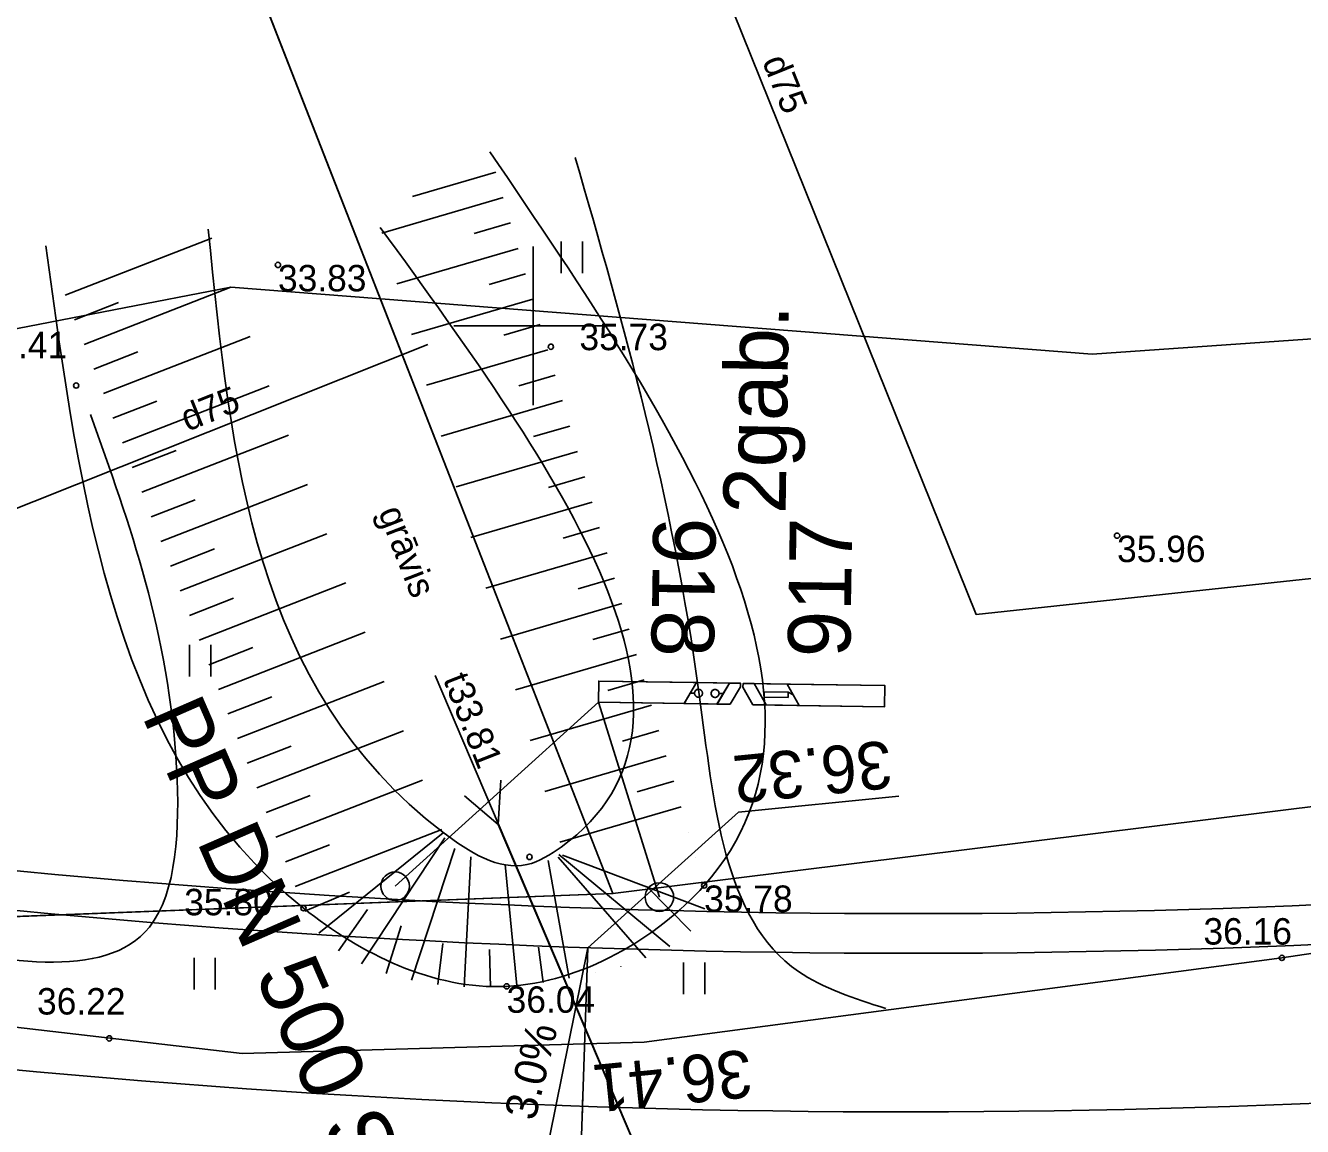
# Model space of a CAD drawing. Extents: x 469981 to 472086, y 246785 to 247785.
# Drawn here: x 470990.4 to 471014.55, y 247184.86 to 247205.68 of the extents above; entities that cross this region are included whole.
import ezdxf

# ---------------------------------------------------------------- set-up
doc = ezdxf.new("R2010")
doc.units = 0
for name, color, linetype in [('0_922', 7, 'Continuous'), ('0_Asfalta_mala', 7, 'Continuous'), ('0_Asfalta_Nomale', 7, 'Continuous'), ('0_caurtekas', 7, 'Continuous'), ('0_Ruut_Braukt', 7, 'Continuous'), ('0_Ruut_nomale', 7, 'Continuous'), ('0_vertikals', 7, 'Continuous'), ('0_vertkals_cipari', 7, 'Continuous'), ('0_Ziimes', 7, 'Continuous'), ('21', 7, 'Continuous'), ('6_piketaza', 7, 'Continuous'), ('CELI_CMAL_####_####_#', 7, 'Continuous'), ('DREN_ELEM_####_####_#', 7, 'Continuous'), ('DREN_VADP_KLKT_####_#', 7, 'Continuous'), ('DREN_VADP_KLKT_TKST_#', 7, 'Continuous'), ('GEOD_ELEM_####_####_#', 7, 'Continuous'), ('HIDG_GRAV_####_####_#', 7, 'Continuous'), ('HIDG_GRAV_####_TKST_#', 7, 'Continuous'), ('RAMI_UZMR_####_####_#', 7, 'Continuous'), ('RELJ_AATZ_####_TKST_#', 7, 'Continuous'), ('RELJ_ELEM_####_####_#', 7, 'Continuous'), ('RELJ_NOGA_####_####_#', 7, 'Continuous'), ('ROBZ_IERR_####_####_#', 7, 'Continuous'), ('ROBZ_PROJ_####_####_#', 7, 'Continuous'), ('TERT_ELEM_####_####_#', 7, 'Continuous'), ('TERT_KONT_####_####_#', 7, 'Continuous'), ('Z_PILD_MELNS', 7, 'Continuous')]:
    doc.layers.add(name, color=color, linetype=linetype)

msp = doc.modelspace()

# ---------------------------------------------------------------- linework, layer by layer
at = {"layer": '0_922'}
msp.add_arc((471007.123, 247365.136), 180, 250.3373, 277.44649, dxfattribs=at)
at = {"layer": '0_Asfalta_mala'}
for radius in [177, 183]:
    msp.add_arc((471007.123, 247365.136), radius, 250.3373, 277.44649, dxfattribs=at)
at = {"layer": '0_Asfalta_Nomale'}
for radius in [176.25, 183.75]:
    msp.add_arc((471007.123, 247365.136), radius, 250.3373, 277.44649, dxfattribs=at)
at = {"layer": '0_caurtekas'}
msp.add_line((470998.149, 247193.392), (471004.628, 247178.166), dxfattribs=at)
at = {"layer": '0_Ruut_Braukt'}
for radius in [177, 183]:
    msp.add_arc((471007.123, 247365.136), radius, 250.3373, 277.44649, dxfattribs=at)
at = {"layer": '0_Ruut_nomale'}
for radius, start, end in [(176.25, 250.3373, 277.44649), (177, 250.33757, 277.4462), (183, 250.33757, 277.44649), (183.75, 250.3373, 277.44649)]:
    msp.add_arc((471007.123, 247365.136), radius, start, end, dxfattribs=at)
at = {"layer": '0_vertikals'}
for p, q in [((471003.884, 247190.806), (471006.915, 247191.11)), ((471001.038, 247188.24), (471003.884, 247190.806))]:
    msp.add_line(p, q, dxfattribs=at)
msp.add_lwpolyline([(471001.038, 247188.24), (470999.832, 247182.28), (471000.831, 247182.244)], close=True, dxfattribs=at)
at = {"layer": '0_Ziimes'}
for q in [(470997.392, 247189.405), (471002.388, 247189.199)]:
    msp.add_line((471001.235, 247192.883), q, dxfattribs=at)
for centre in [(470997.392, 247189.405), (470997.392, 247189.405), (471002.388, 247189.199), (471002.388, 247189.199)]:
    msp.add_circle(centre, 0.27, dxfattribs=at)
at = {"layer": '21'}
msp.add_arc((471007.123, 247365.136), 180, 250.3373, 277.44649, dxfattribs=at)
at = {"layer": '6_piketaza'}
msp.add_lwpolyline([(471000.926, 247184.992), (471000.943, 247185.492)], dxfattribs=at)
at = {"layer": 'CELI_CMAL_####_####_#'}
msp.add_lwpolyline([(470887.869, 247219.351), (470907.988, 247212.254), (470934.743, 247202.499), (470962.898, 247192.42), (470982.559, 247187.627), (470994.5, 247186.238), (471002.099, 247186.455), (471014.161, 247188.048), (471038.308, 247191.645)], dxfattribs=at)
at = {"layer": 'DREN_ELEM_####_####_#'}
msp.add_lwpolyline([(470999.391, 247191.41), (470999.34, 247190.573), (470998.701, 247191.116)], dxfattribs=at)
msp.add_lwpolyline([(470999.391, 247191.41), (470999.34, 247190.573), (470998.701, 247191.116)], dxfattribs=at)
at = {"layer": 'DREN_VADP_KLKT_####_#'}
for points in [[(470998.012, 247199.651), (470980.588, 247192.708), (470867.536, 247231.459)], [(470999.031, 247217.751), (471008.378, 247194.545), (471079.006, 247202.129)], [(471024.755, 247145.454), (471007.332, 247171.821), (470999.34, 247190.573)]]:
    msp.add_lwpolyline(points, dxfattribs=at)
at = {"layer": 'GEOD_ELEM_####_####_#'}
for p, q in [((471000, 247201.5), (471000, 247200)), ((470998.5, 247200), (471000, 247200)), ((471000, 247200), (471000, 247198.5)), ((471000, 247200), (471001.5, 247200))]:
    msp.add_line(p, q, dxfattribs=at)
at = {"layer": 'HIDG_GRAV_####_####_#'}
msp.add_spline([(470993.859, 247201.832), (470998.294, 247190.426), (470999.883, 247189.814), (471000.533, 247190.146), (470997.111, 247201.864)], degree=3, dxfattribs=at)
at = {"layer": 'RAMI_UZMR_####_####_#'}
msp.add_lwpolyline([(470560.64, 247175.144), (470793.366, 247232.231), (470822.25, 247233), (470855.497, 247231.608), (470869.75, 247235.5), (470872.288, 247238.827), (470875.523, 247240.24), (470882.387, 247236.327), (470885.36, 247235.904), (470900.348, 247222.872), (470947.872, 247208.875), (470978.25, 247197.629), (470994.287, 247200.731), (471010.572, 247199.465), (471044.448, 247201.846)], dxfattribs=at)
at = {"layer": 'RELJ_ELEM_####_####_#'}
for centre in [(470995.176, 247201.154), (471000.337, 247199.607), (470991.36, 247198.873), (471011.043, 247196.034), (470999.933, 247189.959), (471003.235, 247189.418), (470995.658, 247188.99), (471014.16, 247188.049), (470999.5, 247187.511), (470991.985, 247186.526)]:
    msp.add_circle(centre, 0.05, dxfattribs=at)
at = {"layer": 'RELJ_NOGA_####_####_#'}
for p, q in [((470999.295, 247202.908), (470997.718, 247202.447)), ((470999.435, 247202.428), (470997.142, 247201.758)), ((470999.576, 247201.948), (470998.887, 247201.747)), ((470990.787, 247201.516), (470990.788, 247201.516)), ((470991.149, 247200.584), (470993.924, 247201.663)), ((470999.716, 247201.468), (470997.422, 247200.798)), ((470990.968, 247201.05), (470990.968, 247201.05)), ((470999.856, 247200.988), (470999.168, 247200.787)), ((470991.512, 247199.652), (470994.287, 247200.731)), ((470999.996, 247200.508), (470997.702, 247199.838)), ((470991.33, 247200.118), (470992.163, 247200.442)), ((471000.136, 247200.028), (470999.448, 247199.827)), ((470991.874, 247198.72), (470994.649, 247199.799)), ((471000.276, 247199.548), (470997.983, 247198.878)), ((470991.693, 247199.186), (470992.525, 247199.51)), ((471000.417, 247199.068), (470999.728, 247198.867)), ((470992.237, 247197.788), (470995.012, 247198.867)), ((470992.055, 247198.254), (470992.888, 247198.578)), ((471000.557, 247198.588), (470998.263, 247197.918)), ((471000.697, 247198.108), (471000.009, 247197.907)), ((470992.599, 247196.856), (470995.374, 247197.935)), ((470992.418, 247197.322), (470993.25, 247197.646)), ((471000.837, 247197.628), (470998.543, 247196.958)), ((471000.977, 247197.148), (471000.289, 247196.947)), ((470992.961, 247195.924), (470995.737, 247197.003)), ((470992.78, 247196.39), (470993.613, 247196.714)), ((471001.117, 247196.668), (470998.824, 247195.999)), ((471001.258, 247196.189), (471000.569, 247195.988)), ((470993.324, 247194.992), (470996.099, 247196.071)), ((470993.143, 247195.458), (470993.975, 247195.782)), ((471001.398, 247195.709), (470999.104, 247195.039)), ((471001.538, 247195.229), (471000.85, 247195.028)), ((470993.686, 247194.06), (470996.461, 247195.139)), ((470993.505, 247194.526), (470994.338, 247194.85)), ((471001.678, 247194.749), (470999.384, 247194.079)), ((470994.049, 247193.128), (470996.824, 247194.207)), ((471001.818, 247194.269), (471001.13, 247194.068)), ((470993.868, 247193.594), (470994.7, 247193.918)), ((471001.958, 247193.789), (470999.665, 247193.119)), ((470994.411, 247192.196), (470997.186, 247193.275)), ((471002.099, 247193.309), (471001.411, 247193.108)), ((470994.23, 247192.662), (470995.063, 247192.986)), ((471002.239, 247192.829), (470999.945, 247192.159)), ((470994.774, 247191.264), (470997.549, 247192.343)), ((471002.379, 247192.349), (471001.691, 247192.148)), ((470994.592, 247191.73), (470995.425, 247192.054)), ((471002.519, 247191.869), (471000.225, 247191.199)), ((470995.136, 247190.332), (470997.911, 247191.411)), ((471002.659, 247191.389), (471001.971, 247191.188)), ((470994.955, 247190.798), (470995.787, 247191.122)), ((471002.799, 247190.909), (471000.506, 247190.239)), ((470995.499, 247189.4), (470998.274, 247190.479)), ((470995.949, 247188.514), (470998.302, 247190.412)), ((471002.94, 247190.429), (471002.939, 247190.429)), ((470995.317, 247189.866), (470996.15, 247190.19)), ((470996.755, 247187.936), (470998.329, 247190.318)), ((470997.704, 247187.628), (470998.518, 247190.115)), ((470998.695, 247187.502), (470998.82, 247189.959)), ((471000.684, 247187.664), (471000.284, 247189.888)), ((471002.131, 247188.051), (471000.476, 247189.953)), ((471002.584, 247188.263), (471000.489, 247190.007)), ((471003.246, 247188.977), (471000.557, 247189.994)), ((471003.08, 247189.949), (471003.079, 247189.949)), ((470999.694, 247187.528), (470999.47, 247189.816)), ((471002.986, 247188.557), (471002.142, 247189.403)), ((471003.22, 247189.469), (471003.22, 247189.469)), ((470995.681, 247188.934), (470996.53, 247189.295)), ((470996.322, 247188.183), (470996.871, 247188.965)), ((470997.221, 247187.755), (470997.504, 247188.657)), ((470998.197, 247187.546), (470998.296, 247188.319)), ((470999.195, 247187.495), (470999.175, 247188.206)), ((471000.191, 247187.586), (471000.1, 247188.255)), ((471001.174, 247187.764), (471001.174, 247187.764)), ((471001.658, 247187.889), (471001.658, 247187.89))]:
    msp.add_line(p, q, dxfattribs=at)
msp.add_spline([(470990.787, 247201.516), (470995.658, 247188.99), (470999.501, 247187.511), (471003.235, 247189.418), (470999.182, 247203.296)], degree=3, dxfattribs=at)
at = {"layer": 'ROBZ_IERR_####_####_#'}
msp.add_lwpolyline([(471513.259, 247488.166), (471524.883, 247464.852), (471341.261, 247348.2), (471124.72, 247213.54), (471093.674, 247200.298), (471050.609, 247195.379), (471001.509, 247189.266), (470977.922, 247249.601)], dxfattribs=at)
at = {"layer": 'ROBZ_PROJ_####_####_#'}
for points in [[(470613.752, 247179.765), (470688.303, 247197.106), (470783.692, 247219.293), (470809.088, 247224.67), (470845.751, 247226.447), (470876.169, 247225.296), (470921.641, 247209.731), (470967.353, 247194.084), (470989.48, 247188.802), (471001.509, 247189.266), (471050.609, 247195.379), (471093.674, 247200.298), (471124.72, 247213.54), (471341.261, 247348.2), (471524.883, 247464.852)], [(470979.699, 247245.057), (471001.509, 247189.266), (470989.48, 247188.802), (470967.353, 247194.084), (470921.641, 247209.731), (470906.814, 247253.012)]]:
    msp.add_lwpolyline(points, dxfattribs=at)
at = {"layer": 'TERT_ELEM_####_####_#'}
for p, q in [((471000.532, 247201), (471000.532, 247201.6)), ((471000.932, 247201), (471000.932, 247201.6)), ((470993.506, 247193.368), (470993.506, 247193.968)), ((470993.906, 247193.368), (470993.906, 247193.968)), ((470993.591, 247187.451), (470993.591, 247188.051)), ((470993.991, 247187.451), (470993.991, 247188.051)), ((471002.846, 247187.365), (471002.846, 247187.965)), ((471003.246, 247187.365), (471003.246, 247187.965))]:
    msp.add_line(p, q, dxfattribs=at)
at = {"layer": 'TERT_KONT_####_####_#'}
for points in [[(471006.668, 247187.092), (471005.018, 247187.792), (471003.143, 247193.028), (471000.798, 247203.187)], [(470987.924, 247188.377), (470992.745, 247188.632), (470993.259, 247191.634), (470991.631, 247198.323)]]:
    msp.add_spline(points, degree=3, dxfattribs=at)
at = {"layer": 'Z_PILD_MELNS'}
for p, q in [((471003.925, 247193.243), (471001.241, 247193.283)), ((471002.854, 247192.859), (471003.09, 247193.255)), ((471003.478, 247192.849), (471003.715, 247193.246)), ((471003.924, 247193.173), (471003.925, 247193.241)), ((471003.728, 247192.846), (471003.924, 247193.173)), ((471003.969, 247193.17), (471003.97, 247193.238)), ((471004.155, 247192.837), (471003.969, 247193.17)), ((471003.97, 247193.24), (471006.654, 247193.199)), ((471004.405, 247192.833), (471004.18, 247193.236)), ((471005.03, 247192.824), (471004.805, 247193.227)), ((471003.728, 247192.846), (471001.235, 247192.883)), ((471004.155, 247192.837), (471006.648, 247192.799))]:
    msp.add_line(p, q, dxfattribs=at)
for points in [[(471002.854, 247192.859), (471003.09, 247193.255), (471001.241, 247193.283), (471001.235, 247192.883)], [(471003.715, 247193.246), (471003.597, 247193.048), (471003.516, 247193.049), (471003.515, 247193.055), (471003.515, 247193.063), (471003.512, 247193.073), (471003.509, 247193.081), (471003.505, 247193.089), (471003.5, 247193.096), (471003.495, 247193.101), (471003.487, 247193.109), (471003.477, 247193.116), (471003.466, 247193.121), (471003.454, 247193.124), (471003.441, 247193.125), (471003.43, 247193.124), (471003.421, 247193.122), (471003.412, 247193.119), (471003.403, 247193.115), (471003.395, 247193.109), (471003.388, 247193.103), (471003.381, 247193.095), (471003.378, 247193.091), (471003.374, 247193.084), (471003.371, 247193.078), (471003.369, 247193.07), (471003.366, 247193.061), (471003.366, 247193.051), (471003.366, 247193.042), (471003.367, 247193.035), (471003.37, 247193.026), (471003.373, 247193.017), (471003.377, 247193.01), (471003.381, 247193.005), (471003.386, 247192.999), (471003.391, 247192.993), (471003.399, 247192.988), (471003.405, 247192.984), (471003.414, 247192.98), (471003.422, 247192.977), (471003.43, 247192.976), (471003.435, 247192.975), (471003.443, 247192.975), (471003.449, 247192.975), (471003.456, 247192.976), (471003.464, 247192.978), (471003.472, 247192.982), (471003.482, 247192.987), (471003.493, 247192.996), (471003.502, 247193.007), (471003.508, 247193.017), (471003.514, 247193.032), (471003.516, 247193.046), (471003.516, 247193.049), (471003.597, 247193.047), (471003.476, 247192.849), (471002.854, 247192.859), (471002.972, 247193.057), (471003.053, 247193.057), (471003.053, 247193.051), (471003.054, 247193.044), (471003.055, 247193.036), (471003.057, 247193.03), (471003.06, 247193.024), (471003.062, 247193.019), (471003.065, 247193.014), (471003.069, 247193.009), (471003.073, 247193.004), (471003.077, 247192.999), (471003.082, 247192.996), (471003.086, 247192.993), (471003.093, 247192.988), (471003.099, 247192.985), (471003.107, 247192.983), (471003.115, 247192.981), (471003.122, 247192.98), (471003.13, 247192.98), (471003.137, 247192.98), (471003.143, 247192.981), (471003.148, 247192.982), (471003.155, 247192.985), (471003.164, 247192.989), (471003.174, 247192.995), (471003.181, 247193.001), (471003.186, 247193.007), (471003.191, 247193.014), (471003.196, 247193.022), (471003.199, 247193.031), (471003.202, 247193.039), (471003.203, 247193.048), (471003.203, 247193.056), (471003.203, 247193.064), (471003.201, 247193.071), (471003.2, 247193.076), (471003.197, 247193.084), (471003.193, 247193.093), (471003.188, 247193.1), (471003.184, 247193.105), (471003.177, 247193.111), (471003.172, 247193.115), (471003.163, 247193.121), (471003.153, 247193.125), (471003.142, 247193.128), (471003.131, 247193.13), (471003.116, 247193.129), (471003.105, 247193.126), (471003.095, 247193.122), (471003.086, 247193.116), (471003.077, 247193.109), (471003.071, 247193.103), (471003.066, 247193.096), (471003.061, 247193.087), (471003.057, 247193.078), (471003.054, 247193.067), (471003.053, 247193.057), (471002.972, 247193.057), (471003.09, 247193.255)], [(471003.728, 247192.846), (471003.924, 247193.173), (471003.925, 247193.241), (471003.715, 247193.246), (471003.478, 247192.849)], [(471004.155, 247192.837), (471003.969, 247193.17), (471003.97, 247193.238), (471004.18, 247193.236), (471004.405, 247192.833)], [(471004.405, 247192.833), (471004.18, 247193.236), (471004.805, 247193.227), (471004.917, 247193.025), (471004.823, 247193.076), (471004.373, 247193.083), (471004.372, 247192.983), (471004.822, 247192.976), (471004.823, 247193.076), (471004.917, 247193.025), (471005.03, 247192.824)], [(471004.372, 247192.983), (471004.373, 247193.083), (471004.823, 247193.076), (471004.822, 247192.976)], [(471005.03, 247192.824), (471004.805, 247193.227), (471006.654, 247193.199), (471006.648, 247192.799)]]:
    msp.add_lwpolyline(points, close=True, dxfattribs=at)
for points in [[(471003.728, 247192.846), (471003.924, 247193.173), (471003.925, 247193.241)], [(471004.155, 247192.837), (471003.969, 247193.17), (471003.97, 247193.238)]]:
    msp.add_lwpolyline(points, dxfattribs=at)
for centre in [(471003.128, 247193.055), (471003.441, 247193.05)]:
    msp.add_circle(centre, 0.075, dxfattribs=at)

# ---------------------------------------------------------------- texts
at = {"layer": '0_caurtekas'}
msp.add_text('PP DN 500 SN8, L=16m', height=1.2, rotation=293.5875, dxfattribs=at).set_placement((470992.595, 247192.636))
at = {"layer": '0_vertkals_cipari'}
for s, height, rotation, p in [('36.32', 0.9, 185.7316, (471006.739, 247192.164)), ('3.0%', 0.5993, 76.1706, (471000.034, 247184.952)), ('36.41', 0.9, 185.7316, (471004.092, 247186.319))]:
    msp.add_text(s, height=height, rotation=rotation, dxfattribs=at).set_placement(p)
at = {"layer": '0_Ziimes'}
for s, rotation, p in [('2gab.', 89.1393, (471004.775, 247196.44)), ('918', 269.1393, (471002.275, 247196.385)), ('917', 89.1393, (471005.997, 247193.725))]:
    msp.add_text(s, height=1.1813, rotation=rotation, dxfattribs=at).set_placement(p)
at = {"layer": 'DREN_VADP_KLKT_TKST_#'}
for s, rotation, p in [('d75', 291.937, (471004.327, 247205.005)), ('d75', 21.7246, (470993.463, 247197.999)), ('t33.81', 291.4106, (470998.293, 247193.32))]:
    msp.add_text(s, height=0.5, rotation=rotation, dxfattribs=at).set_placement(p)
at = {"layer": 'HIDG_GRAV_####_TKST_#'}
msp.add_text('grāvis', height=0.5, rotation=291.2504, dxfattribs=at).set_placement((470997.067, 247196.481))
at = {"layer": 'RELJ_AATZ_####_TKST_#'}
for s, p in [('33.83', (470995.176, 247200.654)), ('35.73', (471000.877, 247199.542)), ('35.41', (470989.517, 247199.39)), ('35.96', (471011.043, 247195.534)), ('35.78', (471003.235, 247188.918)), ('35.80', (470993.403, 247188.855)), ('36.16', (471012.677, 247188.301)), ('36.22', (470990.62, 247186.978)), ('36.04', (470999.5, 247187.011))]:
    msp.add_text(s, height=0.5, dxfattribs=at).set_placement(p)

doc.saveas('drawing.dxf')
